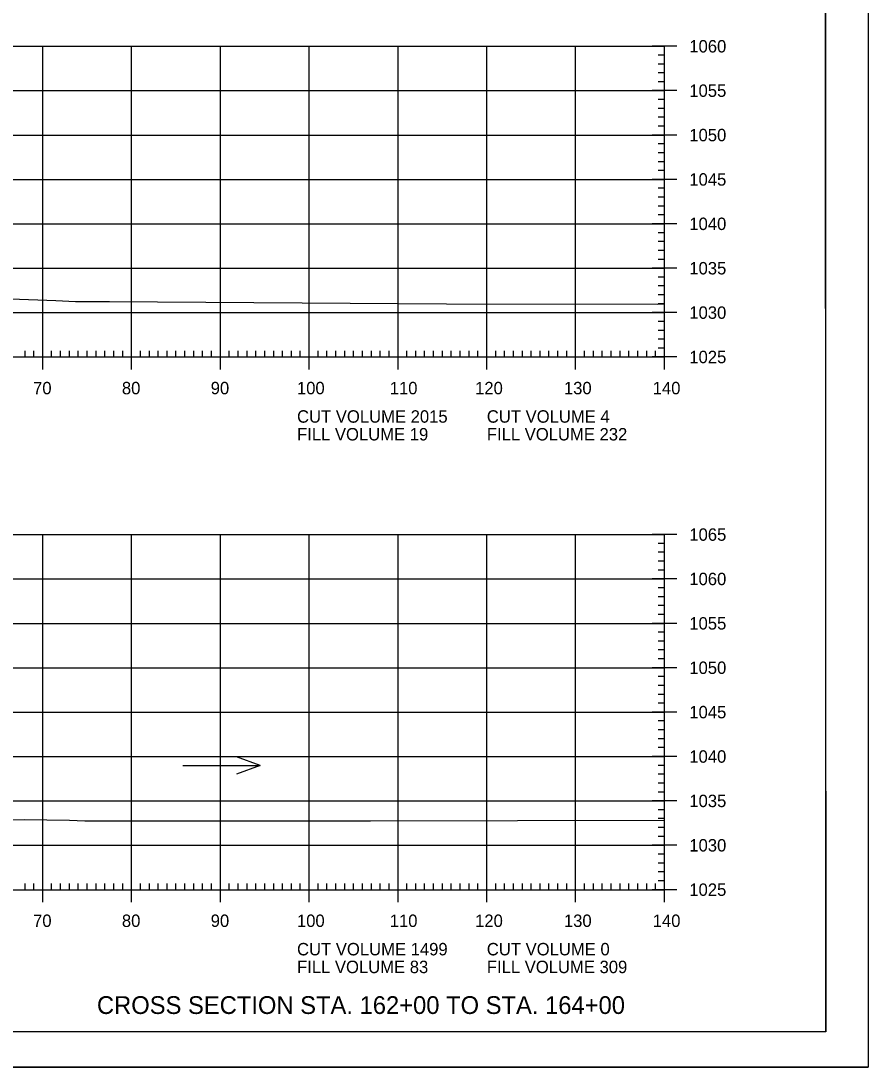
# Model space of a CAD drawing. Extents: x 1322838 to 1324533, y 339903 to 351025.
# Drawn here: x 1323771.3 to 1323866.6, y 345965.4 to 346083.3 of the extents above; entities that cross this region are included whole.
import ezdxf

# ---------------------------------------------------------------- set-up
doc = ezdxf.new("R2010")
doc.units = 0
for name, color, linetype in [('R_Axis', 7, 'Continuous'), ('R_Axis Annot', 7, 'Continuous'), ('R_Border', 7, 'Continuous'), ('R_Draft', 7, 'Continuous'), ('R_Exist Surface', 7, 'Continuous'), ('R_Grid', 7, 'Continuous'), ('R_No Plot', 7, 'Continuous'), ('R_Water Annot', 7, 'Continuous')]:
    doc.layers.add(name, color=color, linetype=linetype)

msp = doc.modelspace()

# ---------------------------------------------------------------- linework, layer by layer
at = {"layer": 'R_Axis'}
for p, q in [((1323845.12, 346080.42), (1323842.32, 346080.42)), ((1323843.72, 346045.42), (1323843.72, 346080.42)), ((1323843.72, 346079.42), (1323843.02, 346079.42)), ((1323843.72, 346078.42), (1323843.02, 346078.42)), ((1323843.72, 346077.42), (1323843.02, 346077.42)), ((1323843.72, 346076.42), (1323843.02, 346076.42)), ((1323845.12, 346075.42), (1323842.32, 346075.42)), ((1323843.72, 346074.42), (1323843.02, 346074.42)), ((1323843.72, 346073.42), (1323843.02, 346073.42)), ((1323843.72, 346072.42), (1323843.02, 346072.42)), ((1323843.72, 346071.42), (1323843.02, 346071.42)), ((1323845.12, 346070.42), (1323842.32, 346070.42)), ((1323843.72, 346069.42), (1323843.02, 346069.42)), ((1323843.72, 346068.42), (1323843.02, 346068.42)), ((1323843.72, 346067.42), (1323843.02, 346067.42)), ((1323845.12, 346065.42), (1323842.32, 346065.42)), ((1323843.72, 346066.42), (1323843.02, 346066.42)), ((1323843.72, 346064.42), (1323843.02, 346064.42)), ((1323843.72, 346063.42), (1323843.02, 346063.42)), ((1323843.72, 346062.42), (1323843.02, 346062.42)), ((1323843.72, 346061.42), (1323843.02, 346061.42)), ((1323845.12, 346060.42), (1323842.32, 346060.42)), ((1323843.72, 346059.42), (1323843.02, 346059.42)), ((1323843.72, 346058.42), (1323843.02, 346058.42)), ((1323843.72, 346057.42), (1323843.02, 346057.42)), ((1323843.72, 346056.42), (1323843.02, 346056.42)), ((1323845.12, 346055.42), (1323842.32, 346055.42)), ((1323843.72, 346054.42), (1323843.02, 346054.42)), ((1323843.72, 346053.42), (1323843.02, 346053.42)), ((1323843.72, 346052.42), (1323843.02, 346052.42)), ((1323843.72, 346051.42), (1323843.02, 346051.42)), ((1323845.12, 346050.42), (1323842.32, 346050.42)), ((1323843.72, 346049.42), (1323843.02, 346049.42)), ((1323843.72, 346048.42), (1323843.02, 346048.42)), ((1323773.72, 346044.02), (1323773.72, 346046.82)), ((1323783.72, 346044.02), (1323783.72, 346046.82)), ((1323793.72, 346044.02), (1323793.72, 346046.82)), ((1323803.72, 346044.02), (1323803.72, 346046.82)), ((1323813.72, 346044.02), (1323813.72, 346046.82)), ((1323823.72, 346044.02), (1323823.72, 346046.82)), ((1323833.72, 346044.02), (1323833.72, 346046.82)), ((1323843.72, 346047.42), (1323843.02, 346047.42)), ((1323843.72, 346044.02), (1323843.72, 346046.82)), ((1323563.72, 346045.42), (1323843.72, 346045.42)), ((1323771.72, 346045.42), (1323771.72, 346046.12)), ((1323772.72, 346045.42), (1323772.72, 346046.12)), ((1323774.72, 346045.42), (1323774.72, 346046.12)), ((1323775.72, 346045.42), (1323775.72, 346046.12)), ((1323776.72, 346045.42), (1323776.72, 346046.12)), ((1323777.72, 346045.42), (1323777.72, 346046.12)), ((1323778.72, 346045.42), (1323778.72, 346046.12)), ((1323779.72, 346045.42), (1323779.72, 346046.12)), ((1323780.72, 346045.42), (1323780.72, 346046.12)), ((1323781.72, 346045.42), (1323781.72, 346046.12)), ((1323782.72, 346045.42), (1323782.72, 346046.12)), ((1323784.72, 346045.42), (1323784.72, 346046.12)), ((1323785.72, 346045.42), (1323785.72, 346046.12)), ((1323786.72, 346045.42), (1323786.72, 346046.12)), ((1323787.72, 346045.42), (1323787.72, 346046.12)), ((1323788.72, 346045.42), (1323788.72, 346046.12)), ((1323789.72, 346045.42), (1323789.72, 346046.12)), ((1323790.72, 346045.42), (1323790.72, 346046.12)), ((1323791.72, 346045.42), (1323791.72, 346046.12)), ((1323792.72, 346045.42), (1323792.72, 346046.12)), ((1323794.72, 346045.42), (1323794.72, 346046.12)), ((1323795.72, 346045.42), (1323795.72, 346046.12)), ((1323796.72, 346045.42), (1323796.72, 346046.12)), ((1323797.72, 346045.42), (1323797.72, 346046.12)), ((1323798.72, 346045.42), (1323798.72, 346046.12)), ((1323799.72, 346045.42), (1323799.72, 346046.12)), ((1323800.72, 346045.42), (1323800.72, 346046.12)), ((1323801.72, 346045.42), (1323801.72, 346046.12)), ((1323802.72, 346045.42), (1323802.72, 346046.12)), ((1323804.72, 346045.42), (1323804.72, 346046.12)), ((1323805.72, 346045.42), (1323805.72, 346046.12)), ((1323806.72, 346045.42), (1323806.72, 346046.12)), ((1323807.72, 346045.42), (1323807.72, 346046.12)), ((1323808.72, 346045.42), (1323808.72, 346046.12)), ((1323809.72, 346045.42), (1323809.72, 346046.12)), ((1323810.72, 346045.42), (1323810.72, 346046.12)), ((1323811.72, 346045.42), (1323811.72, 346046.12)), ((1323812.72, 346045.42), (1323812.72, 346046.12)), ((1323814.72, 346045.42), (1323814.72, 346046.12)), ((1323815.72, 346045.42), (1323815.72, 346046.12)), ((1323816.72, 346045.42), (1323816.72, 346046.12)), ((1323817.72, 346045.42), (1323817.72, 346046.12)), ((1323818.72, 346045.42), (1323818.72, 346046.12)), ((1323819.72, 346045.42), (1323819.72, 346046.12)), ((1323820.72, 346045.42), (1323820.72, 346046.12)), ((1323821.72, 346045.42), (1323821.72, 346046.12)), ((1323822.72, 346045.42), (1323822.72, 346046.12)), ((1323824.72, 346045.42), (1323824.72, 346046.12)), ((1323825.72, 346045.42), (1323825.72, 346046.12)), ((1323826.72, 346045.42), (1323826.72, 346046.12)), ((1323827.72, 346045.42), (1323827.72, 346046.12)), ((1323828.72, 346045.42), (1323828.72, 346046.12)), ((1323829.72, 346045.42), (1323829.72, 346046.12)), ((1323830.72, 346045.42), (1323830.72, 346046.12)), ((1323831.72, 346045.42), (1323831.72, 346046.12)), ((1323832.72, 346045.42), (1323832.72, 346046.12)), ((1323834.72, 346045.42), (1323834.72, 346046.12)), ((1323835.72, 346045.42), (1323835.72, 346046.12)), ((1323836.72, 346045.42), (1323836.72, 346046.12)), ((1323837.72, 346045.42), (1323837.72, 346046.12)), ((1323838.72, 346045.42), (1323838.72, 346046.12)), ((1323839.72, 346045.42), (1323839.72, 346046.12)), ((1323840.72, 346045.42), (1323840.72, 346046.12)), ((1323841.72, 346045.42), (1323841.72, 346046.12)), ((1323845.12, 346045.42), (1323842.32, 346045.42)), ((1323842.72, 346045.42), (1323842.72, 346046.12)), ((1323843.72, 346046.42), (1323843.02, 346046.42)), ((1323845.12, 346025.42), (1323842.32, 346025.42)), ((1323843.72, 345985.42), (1323843.72, 346025.42)), ((1323843.72, 346024.42), (1323843.02, 346024.42)), ((1323843.72, 346023.42), (1323843.02, 346023.42)), ((1323843.72, 346022.42), (1323843.02, 346022.42)), ((1323843.72, 346021.42), (1323843.02, 346021.42)), ((1323845.12, 346020.42), (1323842.32, 346020.42)), ((1323843.72, 346019.42), (1323843.02, 346019.42)), ((1323843.72, 346018.42), (1323843.02, 346018.42)), ((1323843.72, 346017.42), (1323843.02, 346017.42)), ((1323843.72, 346016.42), (1323843.02, 346016.42)), ((1323845.12, 346015.42), (1323842.32, 346015.42)), ((1323843.72, 346014.42), (1323843.02, 346014.42)), ((1323843.72, 346013.42), (1323843.02, 346013.42)), ((1323843.72, 346012.42), (1323843.02, 346012.42)), ((1323843.72, 346011.42), (1323843.02, 346011.42)), ((1323845.12, 346010.42), (1323842.32, 346010.42)), ((1323843.72, 346009.42), (1323843.02, 346009.42)), ((1323843.72, 346008.42), (1323843.02, 346008.42)), ((1323843.72, 346007.42), (1323843.02, 346007.42)), ((1323845.12, 346005.42), (1323842.32, 346005.42)), ((1323843.72, 346006.42), (1323843.02, 346006.42)), ((1323843.72, 346004.42), (1323843.02, 346004.42)), ((1323843.72, 346003.42), (1323843.02, 346003.42)), ((1323843.72, 346002.42), (1323843.02, 346002.42)), ((1323843.72, 346001.42), (1323843.02, 346001.42)), ((1323845.12, 346000.42), (1323842.32, 346000.42)), ((1323843.72, 345999.42), (1323843.02, 345999.42)), ((1323843.72, 345998.42), (1323843.02, 345998.42)), ((1323843.72, 345997.42), (1323843.02, 345997.42)), ((1323843.72, 345996.42), (1323843.02, 345996.42)), ((1323845.12, 345995.42), (1323842.32, 345995.42)), ((1323843.72, 345994.42), (1323843.02, 345994.42)), ((1323843.72, 345993.42), (1323843.02, 345993.42)), ((1323843.72, 345992.42), (1323843.02, 345992.42)), ((1323843.72, 345991.42), (1323843.02, 345991.42)), ((1323845.12, 345990.42), (1323842.32, 345990.42)), ((1323843.72, 345989.42), (1323843.02, 345989.42)), ((1323843.72, 345988.42), (1323843.02, 345988.42)), ((1323773.72, 345984.02), (1323773.72, 345986.82)), ((1323783.72, 345984.02), (1323783.72, 345986.82)), ((1323793.72, 345984.02), (1323793.72, 345986.82)), ((1323803.72, 345984.02), (1323803.72, 345986.82)), ((1323813.72, 345984.02), (1323813.72, 345986.82)), ((1323823.72, 345984.02), (1323823.72, 345986.82)), ((1323833.72, 345984.02), (1323833.72, 345986.82)), ((1323843.72, 345987.42), (1323843.02, 345987.42)), ((1323843.72, 345984.02), (1323843.72, 345986.82)), ((1323563.72, 345985.42), (1323843.72, 345985.42)), ((1323771.72, 345985.42), (1323771.72, 345986.12)), ((1323772.72, 345985.42), (1323772.72, 345986.12)), ((1323774.72, 345985.42), (1323774.72, 345986.12)), ((1323775.72, 345985.42), (1323775.72, 345986.12)), ((1323776.72, 345985.42), (1323776.72, 345986.12)), ((1323777.72, 345985.42), (1323777.72, 345986.12)), ((1323778.72, 345985.42), (1323778.72, 345986.12)), ((1323779.72, 345985.42), (1323779.72, 345986.12)), ((1323780.72, 345985.42), (1323780.72, 345986.12)), ((1323781.72, 345985.42), (1323781.72, 345986.12)), ((1323782.72, 345985.42), (1323782.72, 345986.12)), ((1323784.72, 345985.42), (1323784.72, 345986.12)), ((1323785.72, 345985.42), (1323785.72, 345986.12)), ((1323786.72, 345985.42), (1323786.72, 345986.12)), ((1323787.72, 345985.42), (1323787.72, 345986.12)), ((1323788.72, 345985.42), (1323788.72, 345986.12)), ((1323789.72, 345985.42), (1323789.72, 345986.12)), ((1323790.72, 345985.42), (1323790.72, 345986.12)), ((1323791.72, 345985.42), (1323791.72, 345986.12)), ((1323792.72, 345985.42), (1323792.72, 345986.12)), ((1323794.72, 345985.42), (1323794.72, 345986.12)), ((1323795.72, 345985.42), (1323795.72, 345986.12)), ((1323796.72, 345985.42), (1323796.72, 345986.12)), ((1323797.72, 345985.42), (1323797.72, 345986.12)), ((1323798.72, 345985.42), (1323798.72, 345986.12)), ((1323799.72, 345985.42), (1323799.72, 345986.12)), ((1323800.72, 345985.42), (1323800.72, 345986.12)), ((1323801.72, 345985.42), (1323801.72, 345986.12)), ((1323802.72, 345985.42), (1323802.72, 345986.12)), ((1323804.72, 345985.42), (1323804.72, 345986.12)), ((1323805.72, 345985.42), (1323805.72, 345986.12)), ((1323806.72, 345985.42), (1323806.72, 345986.12)), ((1323807.72, 345985.42), (1323807.72, 345986.12)), ((1323808.72, 345985.42), (1323808.72, 345986.12)), ((1323809.72, 345985.42), (1323809.72, 345986.12)), ((1323810.72, 345985.42), (1323810.72, 345986.12)), ((1323811.72, 345985.42), (1323811.72, 345986.12)), ((1323812.72, 345985.42), (1323812.72, 345986.12)), ((1323814.72, 345985.42), (1323814.72, 345986.12)), ((1323815.72, 345985.42), (1323815.72, 345986.12)), ((1323816.72, 345985.42), (1323816.72, 345986.12)), ((1323817.72, 345985.42), (1323817.72, 345986.12)), ((1323818.72, 345985.42), (1323818.72, 345986.12)), ((1323819.72, 345985.42), (1323819.72, 345986.12)), ((1323820.72, 345985.42), (1323820.72, 345986.12)), ((1323821.72, 345985.42), (1323821.72, 345986.12)), ((1323822.72, 345985.42), (1323822.72, 345986.12)), ((1323824.72, 345985.42), (1323824.72, 345986.12)), ((1323825.72, 345985.42), (1323825.72, 345986.12)), ((1323826.72, 345985.42), (1323826.72, 345986.12)), ((1323827.72, 345985.42), (1323827.72, 345986.12)), ((1323828.72, 345985.42), (1323828.72, 345986.12)), ((1323829.72, 345985.42), (1323829.72, 345986.12)), ((1323830.72, 345985.42), (1323830.72, 345986.12)), ((1323831.72, 345985.42), (1323831.72, 345986.12)), ((1323832.72, 345985.42), (1323832.72, 345986.12)), ((1323834.72, 345985.42), (1323834.72, 345986.12)), ((1323835.72, 345985.42), (1323835.72, 345986.12)), ((1323836.72, 345985.42), (1323836.72, 345986.12)), ((1323837.72, 345985.42), (1323837.72, 345986.12)), ((1323838.72, 345985.42), (1323838.72, 345986.12)), ((1323839.72, 345985.42), (1323839.72, 345986.12)), ((1323840.72, 345985.42), (1323840.72, 345986.12)), ((1323841.72, 345985.42), (1323841.72, 345986.12)), ((1323845.12, 345985.42), (1323842.32, 345985.42)), ((1323842.72, 345985.42), (1323842.72, 345986.12)), ((1323843.72, 345986.42), (1323843.02, 345986.42))]:
    msp.add_line(p, q, dxfattribs=at)
at = {"layer": 'R_Border'}
for q in [(1323861.9, 346174.88), (1323545.72, 345969.42)]:
    msp.add_line((1323861.9, 345969.42), q, dxfattribs=at)
at = {"layer": 'R_Exist Surface'}
for points in [[(1323770.09, 346051.96), (1323775.21, 346051.77), (1323777.4, 346051.69), (1323781.25, 346051.66), (1323819.18, 346051.42), (1323842.92, 346051.38), (1323843.72, 346051.39)], [(1323768.8, 345993.28), (1323771.61, 345993.32), (1323776.74, 345993.24), (1323778.45, 345993.17), (1323810.64, 345993.17), (1323843.72, 345993.25)]]:
    msp.add_lwpolyline(points, dxfattribs=at)
at = {"layer": 'R_Grid'}
for p, q in [((1323563.72, 346080.42), (1323843.72, 346080.42)), ((1323773.72, 346045.42), (1323773.72, 346080.42)), ((1323783.72, 346045.42), (1323783.72, 346080.42)), ((1323793.72, 346045.42), (1323793.72, 346080.42)), ((1323803.72, 346045.42), (1323803.72, 346080.42)), ((1323813.72, 346045.42), (1323813.72, 346080.42)), ((1323823.72, 346045.42), (1323823.72, 346080.42)), ((1323833.72, 346045.42), (1323833.72, 346080.42)), ((1323843.72, 346045.42), (1323843.72, 346080.42)), ((1323563.72, 346075.42), (1323843.72, 346075.42)), ((1323563.72, 346070.42), (1323843.72, 346070.42)), ((1323563.72, 346065.42), (1323843.72, 346065.42)), ((1323563.72, 346060.42), (1323843.72, 346060.42)), ((1323563.72, 346055.42), (1323843.72, 346055.42)), ((1323563.72, 346050.42), (1323843.72, 346050.42)), ((1323563.72, 346045.42), (1323843.72, 346045.42)), ((1323563.72, 346025.42), (1323843.72, 346025.42)), ((1323773.72, 345985.42), (1323773.72, 346025.42)), ((1323783.72, 345985.42), (1323783.72, 346025.42)), ((1323793.72, 345985.42), (1323793.72, 346025.42)), ((1323803.72, 345985.42), (1323803.72, 346025.42)), ((1323813.72, 345985.42), (1323813.72, 346025.42)), ((1323823.72, 345985.42), (1323823.72, 346025.42)), ((1323833.72, 345985.42), (1323833.72, 346025.42)), ((1323843.72, 345985.42), (1323843.72, 346025.42)), ((1323563.72, 346020.42), (1323843.72, 346020.42)), ((1323563.72, 346015.42), (1323843.72, 346015.42)), ((1323563.72, 346010.42), (1323843.72, 346010.42)), ((1323563.72, 346005.42), (1323843.72, 346005.42)), ((1323563.72, 346000.42), (1323843.72, 346000.42)), ((1323563.72, 345995.42), (1323843.72, 345995.42)), ((1323563.72, 345990.42), (1323843.72, 345990.42)), ((1323563.72, 345985.42), (1323843.72, 345985.42))]:
    msp.add_line(p, q, dxfattribs=at)
at = {"layer": 'R_No Plot'}
msp.add_line((1323533.31, 345965.44), (1323866.65, 345965.44), dxfattribs=at)
for points in [[(1323533.31, 346178.78), (1323866.65, 346178.78), (1323866.65, 345965.44), (1323533.31, 345965.44)], [(1323779.64, 346174.88), (1323799.26, 346174.88), (1323799.26, 346165), (1323815.37, 346165), (1323838.57, 346165), (1323838.57, 346132.33), (1323861.77, 346132.33), (1323861.9, 345969.42), (1323545.72, 345969.42), (1323545.72, 346174.88)]]:
    msp.add_lwpolyline(points, close=True, dxfattribs=at)
at = {"layer": 'R_Water Annot'}
for p, q in [((1323798.2, 345999.41), (1323795.54, 346000.37)), ((1323789.51, 345999.41), (1323798.2, 345999.41)), ((1323798.2, 345999.41), (1323795.54, 345998.44))]:
    msp.add_line(p, q, dxfattribs=at)

# ---------------------------------------------------------------- texts
at = {"layer": 'R_Axis Annot'}
for s, p in [('1060', (1323846.52, 346079.72)), ('1055', (1323846.52, 346074.72)), ('1050', (1323846.52, 346069.72)), ('1045', (1323846.52, 346064.72)), ('1040', (1323846.52, 346059.72)), ('1035', (1323846.52, 346054.72)), ('1030', (1323846.52, 346049.72)), ('1025', (1323846.52, 346044.72)), ('70', (1323772.63, 346041.22)), ('80', (1323782.63, 346041.22)), ('90', (1323792.63, 346041.22)), ('100', (1323802.34, 346041.22)), ('110', (1323812.79, 346041.22)), ('120', (1323822.4, 346041.22)), ('130', (1323832.4, 346041.22)), ('140', (1323842.4, 346041.22)), ('CUT VOLUME 2015', (1323802.35, 346038.02)), ('CUT VOLUME 4', (1323823.72, 346038.02)), ('FILL VOLUME 19', (1323802.35, 346036.02)), ('FILL VOLUME 232', (1323823.72, 346036.02)), ('1065', (1323846.52, 346024.72)), ('1060', (1323846.52, 346019.72)), ('1055', (1323846.52, 346014.72)), ('1050', (1323846.52, 346009.72)), ('1045', (1323846.52, 346004.72)), ('1040', (1323846.52, 345999.72)), ('1035', (1323846.52, 345994.72)), ('1030', (1323846.52, 345989.72)), ('1025', (1323846.52, 345984.72)), ('70', (1323772.63, 345981.22)), ('80', (1323782.63, 345981.22)), ('90', (1323792.63, 345981.22)), ('100', (1323802.34, 345981.22)), ('110', (1323812.79, 345981.22)), ('120', (1323822.4, 345981.22)), ('130', (1323832.4, 345981.22)), ('140', (1323842.4, 345981.22)), ('CUT VOLUME 1499', (1323802.35, 345978.02)), ('CUT VOLUME 0', (1323823.72, 345978.02)), ('FILL VOLUME 83', (1323802.35, 345976.02)), ('FILL VOLUME 309', (1323823.72, 345976.02))]:
    msp.add_text(s, height=1.4, dxfattribs=at).set_placement(p)
at = {"layer": 'R_Draft'}
msp.add_text('CROSS SECTION STA. 162+00 TO STA. 164+00', height=2, dxfattribs=at).set_placement((1323779.82, 345971.42))

doc.saveas('drawing.dxf')
